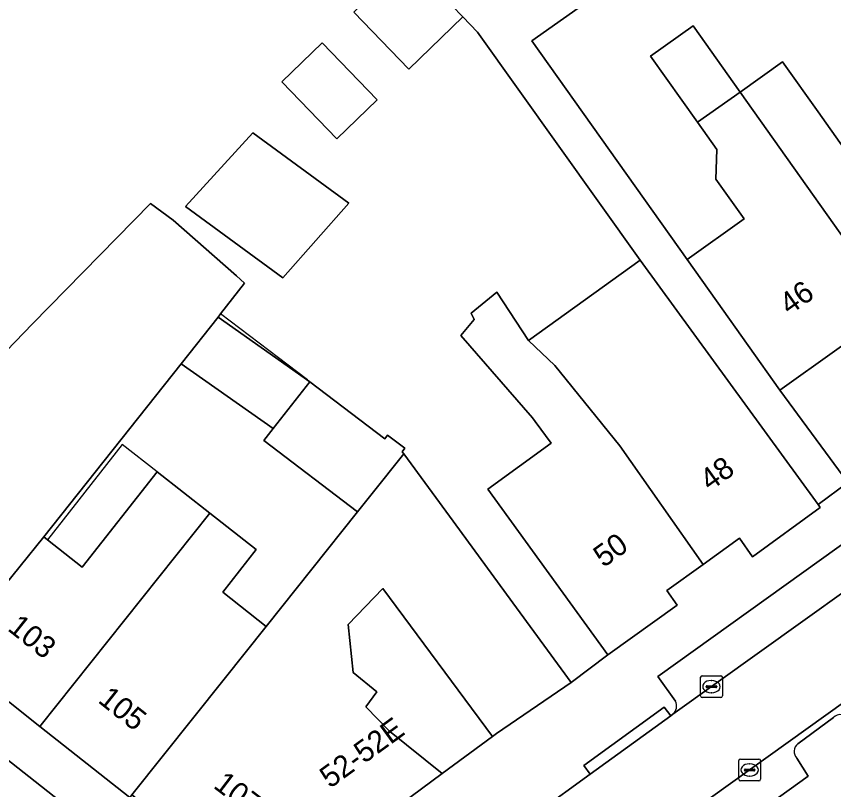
# Model space of a CAD drawing. Extents: x 161881 to 162523, y 381678 to 382381.
# Drawn here: x 162151.2 to 162188.61, y 381861.78 to 381897.16 of the extents above; entities that cross this region are included whole.
import ezdxf

# ---------------------------------------------------------------- set-up
doc = ezdxf.new("R2010")
doc.units = 0
for name, color, linetype in [('IMGEO_Erf', 7, 'Continuous'), ('IMGEO_Fietspad_open', 7, 'Continuous'), ('IMGEO_Hek', 7, 'Continuous'), ('IMGEO_Kolk', 7, 'Continuous'), ('IMGEO_Pand', 7, 'Continuous'), ('IMGEO_Pand_nummerreeks', 7, 'Continuous'), ('IMGEO_Pand_overbouw', 7, 'Continuous'), ('IMGEO_Parkeervlak_open', 7, 'Continuous'), ('IMGEO_Rijbaan_lokaal_open', 7, 'Continuous'), ('IMGEO_Voetpad_open', 7, 'Continuous')]:
    doc.layers.add(name, color=color, linetype=linetype)

msp = doc.modelspace()

# ---------------------------------------------------------------- linework, layer by layer
at = {"layer": 'IMGEO_Erf'}
for points in [[(162192.985, 381899.113), (162194.885, 381900.463), (162197.327, 381902.197), (162199.786, 381898.734), (162202.449, 381900.625), (162205.043, 381902.467), (162199.857, 381909.77), (162197.982, 381912.41), (162174.798, 381896.036), (162181.899, 381886.04), (162184.511, 381887.894), (162183.222, 381889.708), (162183.269, 381891.068), (162182.383, 381892.316), (162180.235, 381895.341), (162182.182, 381896.724), (162184.329, 381893.698), (162186.276, 381895.081), (162187.902, 381892.79), (162189.079, 381891.131), (162192.238, 381893.374), (162195.444, 381895.65)], [(162219.928, 381897.942), (162217.025, 381901.99), (162216.426, 381901.565), (162216.676, 381900.636), (162214.964, 381899.393), (162214.161, 381899.956), (162211.795, 381898.276), (162206.689, 381894.65), (162201.583, 381891.024), (162196.478, 381887.399), (162191.372, 381883.773), (162186.145, 381880.061), (162189.26, 381875.839), (162200.679, 381884.262)], [(162163.351, 381894.161), (162165.198, 381895.948), (162167.72, 381893.341), (162165.874, 381891.554)], [(162162.031, 381891.832), (162166.424, 381888.608), (162163.393, 381885.202), (162158.953, 381888.461)], [(162162.957, 381878.297), (162158.747, 381881.258), (162152.463, 381873.345), (162152.629, 381873.215), (162154.22, 381871.965), (162157.643, 381876.327), (162160.06, 381874.431), (162162.185, 381872.764), (162160.651, 381870.809), (162162.639, 381869.248), (162166.814, 381874.49), (162162.529, 381877.751)], [(162167.982, 381870.977), (162166.397, 381869.331), (162166.625, 381867.135), (162167.706, 381866.247), (162167.194, 381865.56), (162168.29, 381864.451), (162170.693, 381862.513), (162172.99, 381864.214)]]:
    msp.add_lwpolyline(points, close=True, dxfattribs=at)
msp.add_lwpolyline([(162148.345, 381879.368), (162151.949, 381883.093), (162157.343, 381888.594), (162158.379, 381887.832), (162161.278, 381885.287), (162161.652, 381884.958), (162160.554, 381883.557), (162160.435, 381883.405), (162164.642, 381880.446), (162168.072, 381877.837), (162168.196, 381877.999), (162168.987, 381877.397), (162168.868, 381877.239), (162168.933, 381877.15), (162171.2, 381874.055), (162173.642, 381870.716), (162176.595, 381866.681), (162178.278, 381867.945), (162172.782, 381875.521), (162175.682, 381877.625), (162174.953, 381878.63), (162174.834, 381878.795), (162171.545, 381882.56), (162172.152, 381883.286), (162172.027, 381883.588), (162173.19, 381884.548), (162174.639, 381882.333), (162179.758, 381886.011), (162172.317, 381896.44), (162171.643, 381897.136), (162169.174, 381894.747), (162166.651, 381897.354)], dxfattribs=at)
at = {"layer": 'IMGEO_Fietspad_open'}
msp.add_lwpolyline([(162165.207, 381852.621), (162159.359, 381856.676), (162153.733, 381860.844), (162148.22, 381865.171), (162143.628, 381869.029), (162139.164, 381873.055), (162135.64, 381876.643), (162133.655, 381878.876), (162129.811, 381883.512), (162122.303, 381893.442)], dxfattribs=at)
at = {"layer": 'IMGEO_Hek'}
msp.add_lwpolyline([(162164.537, 381880.526), (162160.554, 381883.557)], dxfattribs=at)
at = {"layer": 'IMGEO_Kolk'}
for p, q in [((162182.517, 381866.065), (162182.517, 381866.917)), ((162182.592, 381866.991), (162183.444, 381866.991)), ((162183.518, 381866.917), (162183.518, 381866.065)), ((162182.776, 381866.485), (162182.776, 381866.497)), ((162182.819, 381866.534), (162183.217, 381866.534)), ((162183.005, 381866.771), (162183.03, 381866.771)), ((162183.26, 381866.497), (162183.26, 381866.485)), ((162183.214, 381866.448), (162182.816, 381866.448)), ((162183.028, 381866.211), (162183.003, 381866.211)), ((162183.444, 381865.991), (162182.592, 381865.991)), ((162184.266, 381862.252), (162184.266, 381863.104)), ((162184.341, 381863.178), (162185.193, 381863.178)), ((162185.267, 381863.104), (162185.267, 381862.252)), ((162184.568, 381862.721), (162184.966, 381862.721)), ((162184.754, 381862.958), (162184.779, 381862.958)), ((162184.525, 381862.672), (162184.525, 381862.684)), ((162184.963, 381862.635), (162184.565, 381862.635)), ((162184.777, 381862.398), (162184.752, 381862.398)), ((162185.009, 381862.684), (162185.009, 381862.672)), ((162185.193, 381862.178), (162184.341, 381862.178))]:
    msp.add_line(p, q, dxfattribs=at)
for points in [[(162182.517, 381866.065), (162182.517, 381866.917)], [(162182.592, 381866.991), (162183.444, 381866.991)], [(162183.518, 381866.917), (162183.518, 381866.065)], [(162183.444, 381865.991), (162182.592, 381865.991)], [(162184.266, 381862.252), (162184.266, 381863.104)], [(162184.341, 381863.178), (162185.193, 381863.178)], [(162185.267, 381863.104), (162185.267, 381862.252)], [(162185.193, 381862.178), (162184.341, 381862.178)]]:
    msp.add_lwpolyline(points, dxfattribs=at)
for centre, radius, start, end in [((162182.594, 381866.915), 0.0765, 91.552, 178.448), ((162182.594, 381866.915), 0.0765, 91.552, 178.448), ((162183.442, 381866.915), 0.0765, 1.552, 88.448), ((162183.442, 381866.915), 0.0765, 1.552, 88.448), ((162182.816, 381866.494), 0.0403, 85.8775, 175.7526), ((162182.813, 381866.484), 0.0366, 178.938, 274.7102), ((162183.217, 381866.491), 0.043, 264.8664, 352.4533), ((162183.221, 381866.496), 0.0386, 1.7309, 96.639), ((162182.594, 381866.067), 0.0765, 181.552, 268.448), ((162182.594, 381866.067), 0.0765, 181.552, 268.448), ((162183.442, 381866.067), 0.0765, 271.552, 358.448), ((162183.442, 381866.067), 0.0765, 271.552, 358.448), ((162184.343, 381863.102), 0.0765, 91.552, 178.448), ((162184.343, 381863.102), 0.0765, 91.552, 178.448), ((162185.191, 381863.102), 0.0765, 1.552, 88.448), ((162185.191, 381863.102), 0.0765, 1.552, 88.448), ((162184.565, 381862.681), 0.0403, 85.8775, 175.7526), ((162184.97, 381862.683), 0.0386, 1.7309, 96.639), ((162184.562, 381862.671), 0.0366, 178.938, 274.7102), ((162184.966, 381862.678), 0.043, 264.8664, 352.4533), ((162184.343, 381862.254), 0.0765, 181.552, 268.448), ((162184.343, 381862.254), 0.0765, 181.552, 268.448), ((162185.191, 381862.254), 0.0765, 271.552, 358.448), ((162185.191, 381862.254), 0.0765, 271.552, 358.448)]:
    msp.add_arc(centre, radius, start, end, dxfattribs=at)
for centre, major_axis, ratio, start_param, end_param in [((162183.004, 381866.491), (-0.387, 0.002), 0.722429, 4.712389, 7.853982), ((162183.029, 381866.491), (-0.39, 0.002), 0.717154, 1.570796, 4.712389), ((162184.753, 381862.678), (-0.387, 0.002), 0.722429, 4.712389, 7.853982), ((162184.778, 381862.678), (-0.39, 0.002), 0.717154, 1.570796, 4.712389)]:
    msp.add_ellipse(centre, major_axis=major_axis, ratio=ratio, start_param=start_param, end_param=end_param, dxfattribs=at)
at = {"layer": 'IMGEO_Pand'}
for points in [[(162171.643, 381897.136), (162169.12, 381899.743), (162166.651, 381897.354), (162169.174, 381894.747)], [(162182.383, 381892.316), (162184.329, 381893.698), (162182.182, 381896.724), (162180.235, 381895.341)], [(162163.351, 381894.161), (162165.874, 381891.554), (162167.72, 381893.341), (162165.198, 381895.948)], [(162192.238, 381893.374), (162189.079, 381891.131), (162187.902, 381892.79), (162186.276, 381895.081), (162184.329, 381893.698), (162191.372, 381883.773), (162196.478, 381887.399)], [(162184.329, 381893.698), (162182.383, 381892.316), (162183.269, 381891.068), (162183.222, 381889.708), (162184.511, 381887.894), (162181.899, 381886.04), (162183.25, 381884.138), (162186.145, 381880.061), (162191.372, 381883.773)], [(162166.424, 381888.608), (162162.031, 381891.832), (162158.953, 381888.461), (162163.393, 381885.202)], [(162158.747, 381881.258), (162160.435, 381883.405), (162160.554, 381883.557), (162161.652, 381884.958), (162161.278, 381885.287), (162158.379, 381887.832), (162157.343, 381888.594), (162151.949, 381883.093), (162148.345, 381879.368), (162148.06, 381879.073), (162148.222, 381878.914), (162142.368, 381872.959), (162148.108, 381867.983), (162152.463, 381873.345)], [(162178.829, 381877.515), (162182.635, 381872.084), (162184.296, 381873.278), (162184.9, 381872.437), (162187.997, 381874.692), (162187.895, 381874.832), (162179.758, 381886.011), (162174.639, 381882.333), (162175.845, 381881.19)], [(162178.829, 381877.515), (162175.845, 381881.19), (162174.639, 381882.333), (162173.19, 381884.548), (162172.027, 381883.588), (162172.152, 381883.286), (162171.545, 381882.56), (162174.834, 381878.795), (162174.953, 381878.63), (162175.682, 381877.625), (162172.782, 381875.521), (162178.278, 381867.945), (162181.45, 381870.226), (162180.973, 381870.888), (162182.635, 381872.084)], [(162160.435, 381883.405), (162158.747, 381881.258), (162162.957, 381878.297), (162164.642, 381880.446)], [(162164.642, 381880.446), (162162.957, 381878.297), (162162.529, 381877.751), (162166.814, 381874.49), (162167.482, 381875.329), (162168.933, 381877.15), (162168.868, 381877.239), (162168.987, 381877.397), (162168.196, 381877.999), (162168.072, 381877.837)], [(162167.706, 381866.247), (162166.625, 381867.135), (162166.397, 381869.331), (162167.982, 381870.977), (162172.99, 381864.214), (162173.176, 381864.352), (162176.595, 381866.681), (162173.642, 381870.716), (162171.2, 381874.055), (162168.933, 381877.15), (162167.482, 381875.329), (162166.814, 381874.49), (162162.639, 381869.248), (162160.713, 381866.829), (162156.495, 381861.533), (162162.832, 381856.692), (162170.693, 381862.513), (162168.29, 381864.451), (162167.194, 381865.56)], [(162160.06, 381874.431), (162157.643, 381876.327), (162154.22, 381871.965), (162152.629, 381873.215), (162152.463, 381873.345), (162148.108, 381867.983), (162152.281, 381864.662)], [(162162.639, 381869.248), (162160.651, 381870.809), (162162.185, 381872.764), (162160.06, 381874.431), (162152.281, 381864.662), (162156.403, 381861.418), (162156.495, 381861.533), (162160.713, 381866.829)]]:
    msp.add_lwpolyline(points, close=True, dxfattribs=at)
at = {"layer": 'IMGEO_Pand_overbouw'}
msp.add_lwpolyline([(162156.051, 381877.576), (162152.629, 381873.215), (162154.22, 381871.965), (162157.643, 381876.327)], close=True, dxfattribs=at)
at = {"layer": 'IMGEO_Parkeervlak_open'}
for points in [[(162212.528, 381882.597), (162203.872, 381876.38), (162180.448, 381859.581)], [(162194.635, 381875.39), (162193.827, 381876.453), (162180.57, 381866.951), (162181.366, 381865.831)], [(162181.253, 381865.225), (162195.238, 381875.244)], [(162186.968, 381863.876), (162188.6, 381865.08)], [(162182.228, 381858.647), (162187.449, 381862.392), (162186.929, 381863.221)]]:
    msp.add_lwpolyline(points, dxfattribs=at)
for centre, radius, start, end in [((162180.908, 381865.603), 0.512, 312.3929, 26.4819), ((162188.912, 381864.775), 0.436, 27.9803, 135.6905), ((162187.25, 381863.531), 0.446, 129.2703, 223.9147)]:
    msp.add_arc(centre, radius, start, end, dxfattribs=at)
at = {"layer": 'IMGEO_Rijbaan_lokaal_open'}
for points in [[(162180.448, 381859.581), (162203.872, 381876.38), (162212.528, 381882.597), (162213.447, 381883.269), (162220.372, 381888.318), (162222.952, 381890.129), (162223.84, 381890.752), (162221.475, 381894.082)], [(162221.037, 381893.752), (162218.181, 381891.71), (162206.52, 381883.338), (162205.695, 381882.731), (162201.378, 381879.615), (162196.109, 381875.864), (162195.238, 381875.244), (162181.253, 381865.225), (162181.154, 381865.154), (162177.47, 381862.483), (162175.076, 381860.748), (162174.221, 381860.14), (162173.371, 381859.537), (162172.481, 381858.791), (162169.555, 381856.117), (162167.602, 381854.382), (162171.848, 381851.823), (162172.135, 381852.084), (162172.323, 381852.389)]]:
    msp.add_lwpolyline(points, dxfattribs=at)
at = {"layer": 'IMGEO_Voetpad_open'}
for points in [[(162169.12, 381899.743), (162171.643, 381897.136), (162172.317, 381896.44), (162179.758, 381886.011), (162187.895, 381874.832), (162189.26, 381875.839), (162186.145, 381880.061), (162183.25, 381884.138), (162181.899, 381886.04), (162174.798, 381896.036), (162197.982, 381912.41)], [(162222.611, 381898.266), (162222.089, 381899.341), (162219.928, 381897.942), (162200.679, 381884.262), (162189.26, 381875.839), (162187.895, 381874.832), (162187.997, 381874.692), (162184.9, 381872.437), (162184.296, 381873.278), (162182.635, 381872.084), (162180.973, 381870.888), (162181.45, 381870.226), (162178.278, 381867.945), (162176.595, 381866.681), (162173.176, 381864.352), (162172.99, 381864.214), (162170.693, 381862.513), (162162.832, 381856.692), (162167.236, 381854.058), (162167.602, 381854.382), (162169.555, 381856.117)], [(162181.366, 381865.831), (162180.57, 381866.951), (162193.827, 381876.453), (162194.635, 381875.39)], [(162148.22, 381865.171), (162153.733, 381860.844), (162159.359, 381856.676), (162165.207, 381852.621), (162166.522, 381853.342), (162166.981, 381853.768), (162167.236, 381854.058), (162162.832, 381856.692), (162156.495, 381861.533), (162156.403, 381861.418), (162152.281, 381864.662), (162148.108, 381867.983)], [(162174.221, 381860.14), (162175.076, 381860.748), (162177.47, 381862.483), (162177.177, 381862.887), (162180.861, 381865.558)], [(162180.861, 381865.558), (162181.154, 381865.154), (162181.253, 381865.225)], [(162188.6, 381865.08), (162186.968, 381863.876)], [(162186.929, 381863.221), (162187.449, 381862.392), (162182.228, 381858.647)]]:
    msp.add_lwpolyline(points, dxfattribs=at)
msp.add_lwpolyline([(162181.154, 381865.154), (162180.861, 381865.558), (162177.177, 381862.887), (162177.47, 381862.483)], close=True, dxfattribs=at)
for centre, radius, start, end in [((162180.908, 381865.603), 0.512, 312.3929, 26.4819), ((162188.912, 381864.775), 0.436, 27.9803, 135.6905), ((162187.25, 381863.531), 0.446, 129.2703, 223.9147)]:
    msp.add_arc(centre, radius, start, end, dxfattribs=at)

# ---------------------------------------------------------------- texts
at = {"layer": 'IMGEO_Pand_nummerreeks'}
for s, rotation, p in [('46', 35.3801, (162186.585, 381883.465)), ('48', 35.7199, (162182.946, 381875.411)), ('50', 35.7296, (162178.079, 381871.91)), ('103', 321.4858, (162150.756, 381869.096)), ('105', 321.4915, (162154.894, 381865.803)), ('52-52E', 36.0047, (162165.559, 381861.807)), ('107', 322.6202, (162160.174, 381861.894))]:
    msp.add_text(s, height=1, rotation=rotation, dxfattribs=at).set_placement(p)

doc.saveas('drawing.dxf')
